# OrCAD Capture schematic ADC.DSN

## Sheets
1 ADC: size A
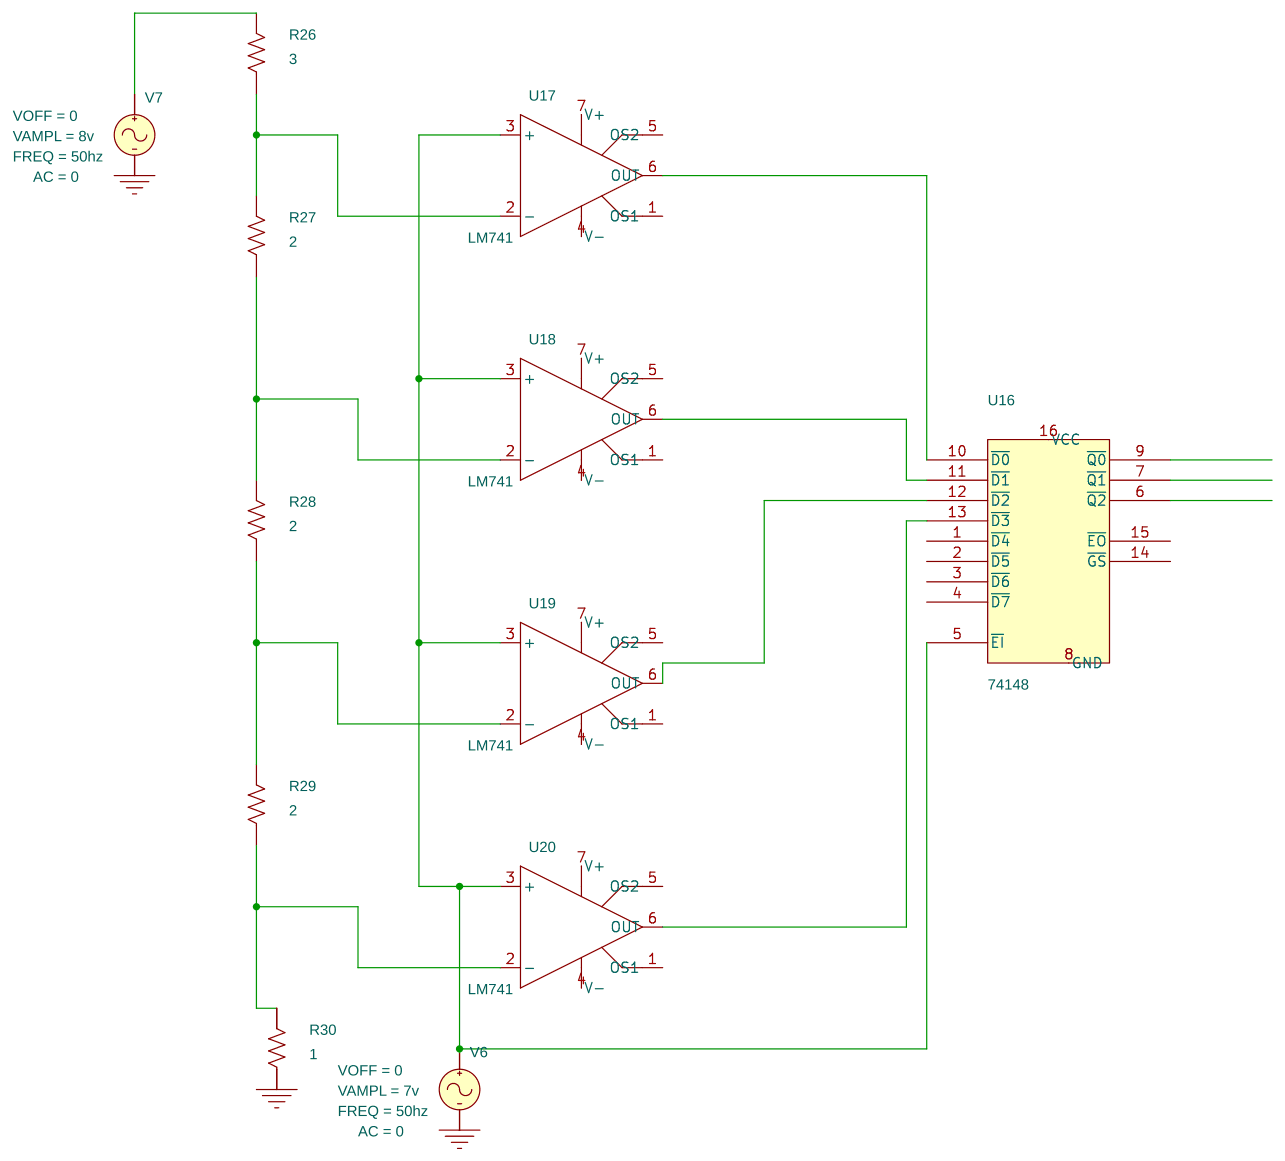
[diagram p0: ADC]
2 ADC2: size A
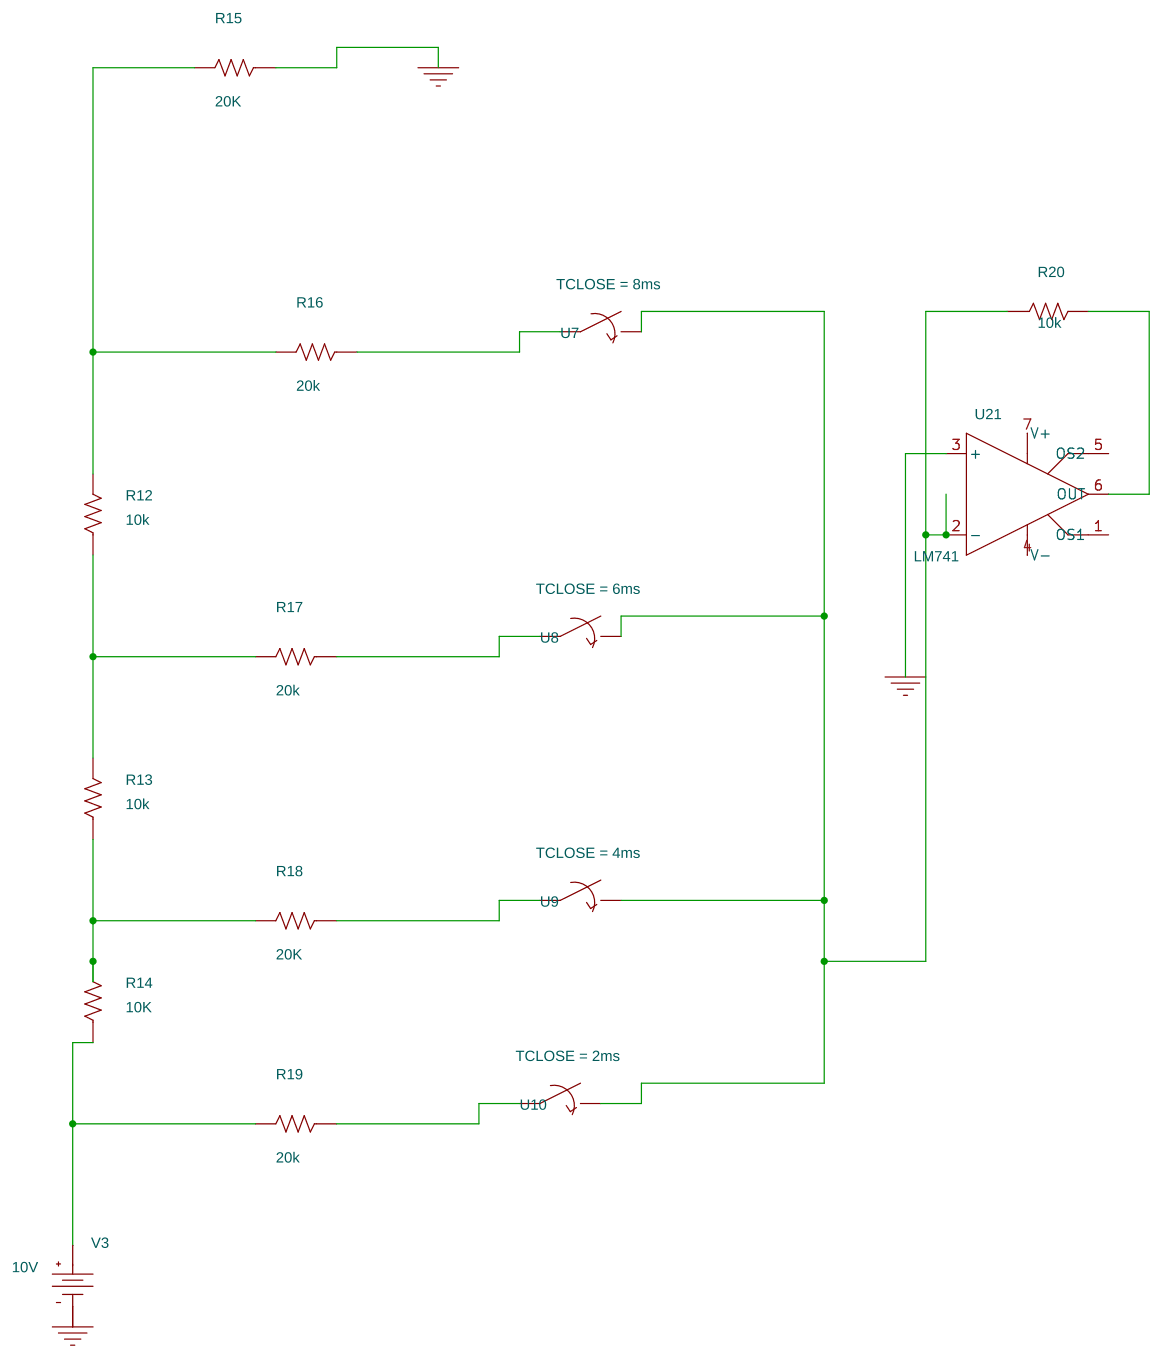
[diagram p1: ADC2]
3 PAGE1: size A
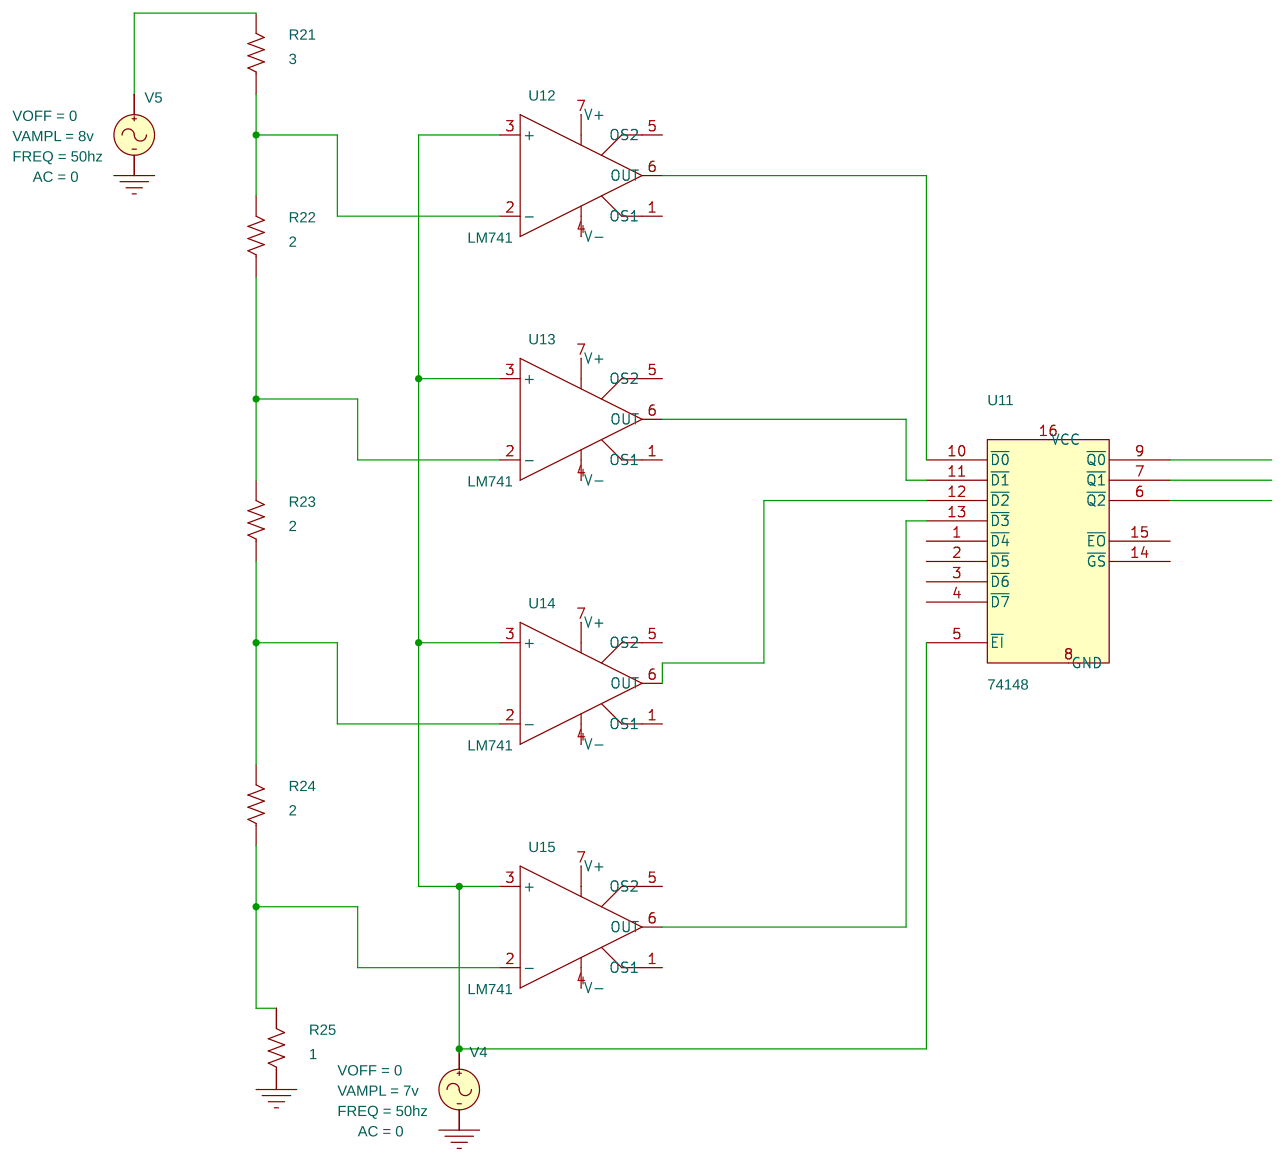
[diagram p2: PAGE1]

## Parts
sheet ADC2
R12  10k  [AX/RC05]
R13  10k  [AX/RC05]
R14  10K  [AX/RC05]
R15  20K  [AX/RC05]
R16  20k  [AX/RC05]
R17  20k  [AX/RC05]
R18  20K  [AX/RC05]
R19  20k  [AX/RC05]
R20  10k  [AX/RC05]
U7  Sw_tClose
U8  Sw_tClose
U9  Sw_tClose
U10  Sw_tClose
U21  LM741  [DIP.100/8/W.300/L.450]
V3  VDC
sheet ADC
R26  3  [AX/RC05]
R27  2  [AX/RC05]
R28  2  [AX/RC05]
R29  2  [AX/RC05]
R30  1  [AX/RC05]
U16  74148
U17  LM741  [DIP.100/8/W.300/L.450]
U18  LM741  [DIP.100/8/W.300/L.450]
U19  LM741  [DIP.100/8/W.300/L.450]
U20  LM741  [DIP.100/8/W.300/L.450]
V6  VSIN
V7  VSIN
sheet PAGE1
R21  3  [AX/RC05]
R22  2  [AX/RC05]
R23  2  [AX/RC05]
R24  2  [AX/RC05]
R25  1  [AX/RC05]
U11  74148
U12  LM741  [DIP.100/8/W.300/L.450]
U13  LM741  [DIP.100/8/W.300/L.450]
U14  LM741  [DIP.100/8/W.300/L.450]
U15  LM741  [DIP.100/8/W.300/L.450]
V4  VSIN
V5  VSIN

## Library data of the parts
R12-R30 = r
U7 = Sw_tClose: TCLOSE: 8ms
U8 = Sw_tClose: TCLOSE: 6ms
U9 = Sw_tClose: TCLOSE: 4ms
U10 = Sw_tClose: TCLOSE: 2ms
U12-U15 U17-U21 = LM741
V3 = VDC: DC: 10V
U11 U16 = 74148
V4 V6 = VSIN: AC: 0; FREQ: 50hz; VAMPL: 7v; VOFF: 0
V5 V7 = VSIN: AC: 0; FREQ: 50hz; VAMPL: 8v; VOFF: 0

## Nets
GND: U11.8(GND) U16.8(GND)
VCC: U11.16(VCC) U16.16(VCC)
0: R15.1 R25.1 R30.1 U21.3(+) V3.1(-) V4.2(-) V5.2(-) V6.2(-) V7.2(-)
V+: U12.7(V+) U13.7(V+) U14.7(V+) U15.7(V+) U17.7(V+) U18.7(V+) U19.7(V+) U20.7(V+) U21.7(V+)
V-: U12.4(V-) U13.4(V-) U14.4(V-) U15.4(V-) U17.4(V-) U18.4(V-) U19.4(V-) U20.4(V-) U21.4(V-)
N04122: R14.1 R19.2 V3.0(+)
N04129: R13.1 R14.2 R18.2
N04138: R12.1 R13.2 R17.2
N04142: R12.2 R15.2 R16.2
N04181: R16.1 U7.1
N04204: R17.1 U8.1
N04241: R19.1 U10.1
N04259: R18.1 U9.1
N04314: R20.1 U7.2 U8.2 U9.2 U10.2 U21.2(-)
N04442: R20.2 U21.6(OUT)
N13376: U11.5(~{EI}) U12.3(+) U13.3(+) U14.3(+) U15.3(+) V4.1(+)
N13439: R21.2 V5.1(+)
N13446: R21.1 R22.2 U12.2(-)
N13450: R22.1 R23.2 U13.2(-)
N13454: R23.1 R24.2 U14.2(-)
N13458: R24.1 R25.2 U15.2(-)
N13747: U11.10(~{D0}) U12.6(OUT)
N13754: U11.11(~{D1}) U13.6(OUT)
N13766: U11.12(~{D2}) U14.6(OUT)
N13784: U11.13(~{D3}) U15.6(OUT)
N14962: U16.5(~{EI}) U17.3(+) U18.3(+) U19.3(+) U20.3(+) V6.1(+)
N14994: R26.2 V7.1(+)
N15010: R26.1 R27.2 U17.2(-)
N15014: R27.1 R28.2 U18.2(-)
N15018: R28.1 R29.2 U19.2(-)
N15022: R29.1 R30.2 U20.2(-)
N15098: U16.10(~{D0}) U17.6(OUT)
N15106: U16.11(~{D1}) U18.6(OUT)
N15118: U16.12(~{D2}) U19.6(OUT)
N15134: U16.13(~{D3}) U20.6(OUT)

Not connected (* = marked no-connect by the designer): U11 1(~{D4}) 2(~{D5}) 3(~{D6}) 4(~{D7}) 6(~{Q2}) 7(~{Q1}) 9(~{Q0}) 14(~{GS}) 15(~{EO}); U12 1(OS1) 5(OS2); U13 1(OS1) 5(OS2); U14 1(OS1) 5(OS2); U15 1(OS1) 5(OS2); U16 1(~{D4}) 2(~{D5}) 3(~{D6}) 4(~{D7}) 6(~{Q2}) 7(~{Q1}) 9(~{Q0}) 14(~{GS}) 15(~{EO}); U17 1(OS1) 5(OS2); U18 1(OS1) 5(OS2); U19 1(OS1) 5(OS2); U20 1(OS1) 5(OS2); U21 1(OS1) 5(OS2)
